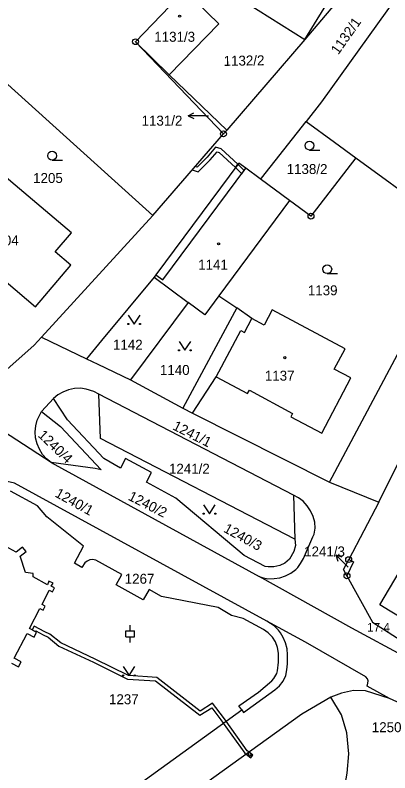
# Model space of a CAD drawing. Extents: x -562167 to -556918, y -1077891 to -1070763.
# Drawn here: x -559284.2 to -559220.3, y -1075093.3 to -1074964 of the extents above; entities that cross this region are included whole.
import ezdxf

# ---------------------------------------------------------------- set-up
doc = ezdxf.new("R2010")
doc.units = 0
for name, color, linetype in [('Hranice parcel', 7, 'Continuous'), ('Parcelní čísla', 7, 'Continuous'), ('Pop  PČ popisy', 7, 'Continuous'), ('Vnitřní kresba', 7, 'Continuous'), ('Věcná břemena k části', 7, 'Continuous'), ('Značky bodu BP', 7, 'Continuous'), ('Značky budov', 7, 'Continuous'), ('Značky kultur', 7, 'Continuous')]:
    doc.layers.add(name, color=color, linetype=linetype)

msp = doc.modelspace()

# ---------------------------------------------------------------- linework, layer by layer
at = {"layer": 'Hranice parcel'}
for p, q in [((-559263.69, -1074968.56), (-559255.3, -1074959.84)), ((-559257.93, -1074974.19), (-559263.69, -1074968.56)), ((-559248.71, -1074984.29), (-559263.69, -1074968.56)), ((-559260.73, -1074998.22), (-559290.13, -1074971.64)), ((-559248.14, -1074983.63), (-559257.93, -1074974.19)), ((-559260.73, -1074998.22), (-559248.71, -1074984.29)), ((-559248.71, -1074984.29), (-559248.14, -1074983.63)), ((-559237.44, -1074995.64), (-559242.45, -1074991.95)), ((-559237.44, -1074995.64), (-559249.47, -1075011.92)), ((-559279.73, -1075018.96), (-559260.73, -1074998.22)), ((-559260.54, -1075008.75), (-559254.74, -1075013.07)), ((-559249.47, -1075011.92), (-559246.45, -1075013.99)), ((-559254.74, -1075013.07), (-559264.53, -1075026.27)), ((-559246.45, -1075013.99), (-559255.63, -1075031.07)), ((-559279.73, -1075018.96), (-559272.06, -1075022.65)), ((-559264.53, -1075026.27), (-559255.63, -1075031.07)), ((-559277.69, -1075029.45), (-559279.74, -1075031.69)), ((-559236.78, -1075045.92), (-559269.97, -1075028.68)), ((-559255.63, -1075031.07), (-559253.99, -1075031.95)), ((-559253.99, -1075031.95), (-559230.63, -1075043.7)), ((-559278.07, -1075040.36), (-559242.63, -1075059.8)), ((-559222.24, -1075047.15), (-559218.86, -1075040.37)), ((-559230.63, -1075043.7), (-559222.24, -1075047.15)), ((-559236.78, -1075045.92), (-559236.54, -1075053.44)), ((-559222.24, -1075047.15), (-559227.36, -1075056.94)), ((-559206.67, -1075087.05), (-559220.42, -1075080.63)), ((-559272.93, -1075102.34), (-559245.59, -1075082.57))]:
    msp.add_line(p, q, dxfattribs=at)
for points in [[(-559238.79, -1074952.13), (-559240.62, -1074955.11), (-559244.8, -1074961.93), (-559234.81, -1074968.19), (-559226.15, -1074954.04), (-559222.92, -1074948.76), (-559232.94, -1074942.58), (-559236.16, -1074947.84), (-559238.79, -1074952.13)], [(-559216.47, -1074946.43), (-559234.81, -1074968.19), (-559248.14, -1074983.63)], [(-559217.7, -1074958.78), (-559231.97, -1074978.81), (-559234.61, -1074982.17)], [(-559255.3, -1074959.84), (-559249.47, -1074965.49), (-559257.93, -1074974.19)], [(-559242.45, -1074991.95), (-559242.24, -1074991.85), (-559234.61, -1074982.17)], [(-559234.61, -1074982.17), (-559229.78, -1074985.69), (-559226.12, -1074988.37)], [(-559307.05, -1075008), (-559298.84, -1074998.38), (-559280.72, -1075013.78), (-559274.69, -1075006.71), (-559277.38, -1075004.42), (-559274.61, -1075001.17), (-559284.23, -1074993.04), (-559289.72, -1074988.39), (-559292.44, -1074991.58), (-559292.75, -1074991.32), (-559296.55, -1074988.08), (-559309.68, -1075005.76)], [(-559242.45, -1074991.95), (-559244.9, -1074990.14), (-559246.1, -1074989.26), (-559260.23, -1075008.33), (-559260.54, -1075008.75)], [(-559226.12, -1074988.37), (-559233.79, -1074998.32), (-559237.44, -1074995.64)], [(-559226.12, -1074988.37), (-559213.81, -1074997.38), (-559208.23, -1075001.46)], [(-559230.63, -1075043.7), (-559208.82, -1075002.71), (-559208.23, -1075001.46)], [(-559260.54, -1075008.75), (-559269.5, -1075019.57), (-559272.06, -1075022.65)], [(-559249.47, -1075011.92), (-559251.89, -1075015.18), (-559254.74, -1075013.07)], [(-559253.99, -1075031.95), (-559249.93, -1075025.75), (-559244.61, -1075028.6), (-559244.29, -1075028), (-559236.93, -1075031.98), (-559237.24, -1075032.56), (-559231.96, -1075035.39), (-559226.97, -1075025.93), (-559229.81, -1075024.44), (-559227.96, -1075020.99), (-559240.41, -1075014.33), (-559241.74, -1075016.92), (-559243.87, -1075015.81), (-559246.45, -1075013.99)], [(-559278.07, -1075040.36), (-559293.43, -1075030.4), (-559312.19, -1075014.25)], [(-559286.13, -1075024.94), (-559280.96, -1075020.32), (-559279.73, -1075018.96)], [(-559272.06, -1075022.65), (-559270.1, -1075023.59), (-559264.53, -1075026.27)], [(-559269.97, -1075028.68), (-559270.78, -1075028.26), (-559272.09, -1075027.83), (-559273.08, -1075027.71), (-559274.11, -1075027.75), (-559275.1, -1075027.95), (-559276.08, -1075028.34), (-559276.94, -1075028.84), (-559277.69, -1075029.45)], [(-559236.54, -1075053.44), (-559236.41, -1075054.55), (-559236.69, -1075055.54), (-559237.45, -1075056.88), (-559238.22, -1075057.52), (-559239.12, -1075057.97), (-559240.1, -1075058.19), (-559241.1, -1075058.18), (-559241.6, -1075058.1), (-559245.16, -1075056.23), (-559256.82, -1075046.45), (-559261.82, -1075043.7), (-559260.95, -1075042.1), (-559265.37, -1075039.7), (-559266.27, -1075041.32), (-559269.09, -1075039.71), (-559275.26, -1075033.07), (-559277.69, -1075029.45)], [(-559236.54, -1075053.44), (-559269.65, -1075036.28), (-559269.97, -1075028.68)], [(-559278.07, -1075040.36), (-559278.85, -1075039.73), (-559279.52, -1075038.99), (-559280.08, -1075038.08), (-559280.48, -1075037.16), (-559280.72, -1075036.15), (-559280.78, -1075035.13), (-559280.69, -1075034.12), (-559280.43, -1075033.14), (-559279.74, -1075031.69)], [(-559279.74, -1075031.69), (-559276.45, -1075034.2), (-559269.53, -1075041.63), (-559270.56, -1075041.41), (-559278.07, -1075040.36)], [(-559241.32, -1075067.43), (-559284.34, -1075043.87), (-559286.56, -1075043.36), (-559289.11, -1075043.57), (-559289.97, -1075044.01)], [(-559245.59, -1075082.57), (-559246.08, -1075081.92), (-559242.72, -1075079.56), (-559240.46, -1075077.6), (-559240.11, -1075077.24), (-559239.62, -1075076.38), (-559239.49, -1075075.9), (-559239.32, -1075074.43), (-559239.34, -1075072.92), (-559239.51, -1075071.96), (-559239.86, -1075071), (-559240.37, -1075070.18), (-559241.06, -1075069.45), (-559241.88, -1075068.89), (-559245.36, -1075066.98), (-559247.31, -1075066.48), (-559249.62, -1075065.14), (-559259.25, -1075063.24), (-559261.39, -1075062.03), (-559262.36, -1075063.8), (-559266.98, -1075061.26), (-559266.05, -1075059.46), (-559270.48, -1075057.03), (-559271, -1075056.95), (-559271.48, -1075057), (-559271.95, -1075057.18), (-559272.35, -1075057.48), (-559272.83, -1075058.28), (-559274.09, -1075057.56), (-559272.55, -1075054.65), (-559278.78, -1075049.63), (-559280.41, -1075047.78), (-559284.98, -1075045.28)], [(-559242.63, -1075059.8), (-559242.13, -1075059.99), (-559241.12, -1075060.21), (-559240.08, -1075060.19), (-559239.08, -1075060.05), (-559238.12, -1075059.72), (-559237.21, -1075059.25), (-559236.39, -1075058.63), (-559236.03, -1075058.26), (-559235.55, -1075057.59), (-559235.06, -1075056.73), (-559233.45, -1075053.07), (-559233.26, -1075052.58), (-559233.08, -1075051.58), (-559233.14, -1075050.57), (-559233.44, -1075049.56), (-559233.85, -1075048.62), (-559234.41, -1075047.76), (-559235.1, -1075046.99), (-559235.9, -1075046.42), (-559236.78, -1075045.92)], [(-559196.58, -1075063.63), (-559203.73, -1075075.69), (-559220.31, -1075065.75), (-559222.06, -1075064.67), (-559218.74, -1075059.06), (-559213.37, -1075049.98), (-559200.62, -1075057.57), (-559200.89, -1075058.05), (-559197.29, -1075060.19)], [(-559284.83, -1075074.62), (-559283.63, -1075075.25), (-559283.19, -1075074.41), (-559284.39, -1075073.78), (-559282.18, -1075069.57), (-559280.98, -1075070.2), (-559280.54, -1075069.35), (-559281.74, -1075068.72), (-559279.98, -1075065.27), (-559279.43, -1075065.55), (-559279.08, -1075064.86), (-559279.62, -1075064.58), (-559278.4, -1075062.18), (-559277.84, -1075062.46), (-559277.49, -1075061.77), (-559278.04, -1075061.49), (-559277.72, -1075060.94), (-559278.44, -1075060.61), (-559278.67, -1075061.23), (-559281.16, -1075059.88), (-559281.12, -1075059.3), (-559282.45, -1075059.16), (-559283.33, -1075056.38), (-559282.32, -1075055.53), (-559282.93, -1075054.8), (-559284.03, -1075055.66), (-559286.53, -1075054.32)], [(-559227.65, -1075059.72), (-559228.25, -1075058.63), (-559227.36, -1075056.94)], [(-559227.36, -1075056.94), (-559226.52, -1075057.33), (-559227.65, -1075059.72)], [(-559215.74, -1075072.47), (-559216.62, -1075073.49), (-559217.48, -1075073.54), (-559217.55, -1075073.66), (-559226.8, -1075068.62), (-559242.63, -1075059.8)], [(-559227.65, -1075059.72), (-559223.32, -1075067.62), (-559215.74, -1075072.47)], [(-559245.59, -1075082.57), (-559245.27, -1075083.01), (-559241.99, -1075080.67), (-559239.93, -1075079.16), (-559239.16, -1075078.5), (-559238.53, -1075077.68), (-559238.1, -1075076.73), (-559237.9, -1075075.73), (-559237.79, -1075074.74), (-559237.77, -1075073.2), (-559237.87, -1075072.17), (-559238.12, -1075071.17), (-559238.5, -1075070.26), (-559238.99, -1075069.41), (-559239.31, -1075068.98), (-559240.06, -1075068.27), (-559241.32, -1075067.43)], [(-559220.42, -1075080.63), (-559224.2, -1075078.56), (-559224.07, -1075078), (-559224.05, -1075077.6), (-559224.18, -1075077.26), (-559224.45, -1075076.95), (-559234.7, -1075071.05), (-559241.32, -1075067.43)], [(-559220.42, -1075080.63), (-559224.47, -1075079.31), (-559226.54, -1075079.27), (-559228.58, -1075079.75), (-559230.4, -1075080.42)], [(-559230.4, -1075080.42), (-559235.33, -1075083.33), (-559264.92, -1075104.67)], [(-559230.7, -1075102.99), (-559229.22, -1075099.97), (-559229.03, -1075099.36), (-559228.19, -1075096.62), (-559227.62, -1075093.4), (-559227.33, -1075090.1), (-559227.69, -1075086.51), (-559228.61, -1075083.41), (-559230.4, -1075080.42)]]:
    msp.add_lwpolyline(points, dxfattribs=at)
at = {"layer": 'Pop  PČ popisy'}
for p, q in [((-559254.73, -1074981.18), (-559253.73, -1074980.68)), ((-559251.73, -1074981.18), (-559254.73, -1074981.18)), ((-559254.73, -1074981.18), (-559253.73, -1074981.68)), ((-559251.73, -1074981.18), (-559251.23, -1074981.18)), ((-559227.46, -1075058.24), (-559229.58, -1075056.12)), ((-559229.58, -1075056.12), (-559228.52, -1075056.47)), ((-559229.58, -1075056.12), (-559229.23, -1075057.18))]:
    msp.add_line(p, q, dxfattribs=at)
at = {"layer": 'Vnitřní kresba'}
for p, q in [((-559259.04, -1075009.22), (-559244.9, -1074990.14)), ((-559260.23, -1075008.33), (-559259.04, -1075009.22)), ((-559245.11, -1075018.17), (-559243.87, -1075015.81)), ((-559249.93, -1075025.75), (-559245.75, -1075017.83)), ((-559245.75, -1075017.83), (-559245.11, -1075018.17))]:
    msp.add_line(p, q, dxfattribs=at)
at = {"layer": 'Věcná břemena k části'}
for points in [[(-559253.01, -1074990.78), (-559250.98, -1074988.73), (-559249.8, -1074987.37), (-559249.45, -1074987.47), (-559246.65, -1074990), (-559246.23, -1074989.43), (-559249.11, -1074986.84), (-559250.04, -1074986.57), (-559251.5, -1074988.25), (-559253.19, -1074989.98), (-559253.52, -1074989.87), (-559254.02, -1074990.44)], [(-559245.6, -1074991.08), (-559245.17, -1074990.51), (-559246.23, -1074989.43), (-559246.65, -1074990)], [(-559281.3, -1075068.95), (-559280.77, -1075069.23), (-559280.7, -1075069.11), (-559279.42, -1075069.79), (-559278.6, -1075070.19), (-559276.74, -1075071.69), (-559270.83, -1075074.45), (-559265.03, -1075077.32), (-559260.28, -1075077.62), (-559252.73, -1075083.5), (-559250.7, -1075082.26), (-559249.16, -1075084.26), (-559248.74, -1075084.85), (-559245.08, -1075089.97), (-559244.82, -1075090.17), (-559244.31, -1075089.81), (-559244.64, -1075089.55), (-559248.25, -1075084.5), (-559248.68, -1075083.9), (-559250.56, -1075081.46), (-559252.69, -1075082.78), (-559260.06, -1075077.04), (-559264.87, -1075076.72), (-559270.57, -1075073.91), (-559276.42, -1075071.17), (-559278.28, -1075069.69), (-559279.14, -1075069.25), (-559280.94, -1075068.29)], [(-559243.67, -1075090.31), (-559244.31, -1075089.81), (-559244.82, -1075090.17), (-559244.04, -1075090.78)], [(-559244.26, -1075090.5), (-559243.92, -1075090.28), (-559244.24, -1075089.76), (-559244.57, -1075090)]]:
    msp.add_lwpolyline(points, close=True, dxfattribs=at)
at = {"layer": 'Značky bodu BP'}
for centre, radius in [((-559263.69, -1074968.56), 0.5), ((-559263.69, -1074968.56), 0.0303), ((-559248.71, -1074984.29), 0.5), ((-559248.71, -1074984.29), 0.0303), ((-559233.79, -1074998.32), 0.5), ((-559233.79, -1074998.32), 0.0303), ((-559227.36, -1075056.94), 0.5), ((-559227.36, -1075056.94), 0.0303), ((-559227.65, -1075059.72), 0.5), ((-559227.65, -1075059.72), 0.0303)]:
    msp.add_circle(centre, radius, dxfattribs=at)
at = {"layer": 'Značky budov'}
for centre in [(-559256.17, -1074964.21), (-559249.53, -1075003.07), (-559238.24, -1075022.48)]:
    msp.add_circle(centre, 0.175, dxfattribs=at)
at = {"layer": 'Značky kultur'}
for p, q in [((-559234.05, -1074987.04), (-559232.3, -1074987.04)), ((-559277.91, -1074988.76), (-559276.16, -1074988.76)), ((-559231.01, -1075008.14), (-559229.26, -1075008.14)), ((-559264.61, -1075069.1), (-559264.61, -1075068.1)), ((-559265.36, -1075069.1), (-559263.86, -1075069.1)), ((-559265.36, -1075070.1), (-559265.36, -1075069.1)), ((-559263.86, -1075070.1), (-559263.86, -1075069.1)), ((-559265.36, -1075070.1), (-559263.86, -1075070.1)), ((-559264.61, -1075071.1), (-559264.61, -1075070.1))]:
    msp.add_line(p, q, dxfattribs=at)
for points in [[(-559264.92, -1075015.24), (-559263.92, -1075016.74), (-559262.92, -1075015.24)], [(-559256.28, -1075019.72), (-559255.28, -1075021.22), (-559254.28, -1075019.72)], [(-559252.09, -1075047.61), (-559251.09, -1075049.11), (-559250.09, -1075047.61)], [(-559265.8, -1075075.19), (-559264.8, -1075076.69), (-559263.8, -1075075.19)]]:
    msp.add_lwpolyline(points, dxfattribs=at)
for centre, radius in [((-559234.05, -1074986.29), 0.75), ((-559277.91, -1074988.01), 0.75), ((-559231.01, -1075007.39), 0.75), ((-559264.92, -1075016.74), 0.1), ((-559262.92, -1075016.74), 0.1), ((-559256.28, -1075021.22), 0.1), ((-559254.28, -1075021.22), 0.1), ((-559252.09, -1075049.11), 0.1), ((-559250.09, -1075049.11), 0.1), ((-559265.8, -1075076.69), 0.1), ((-559263.8, -1075076.69), 0.1)]:
    msp.add_circle(centre, radius, dxfattribs=at)

# ---------------------------------------------------------------- texts
at = {"layer": 'Parcelní čísla'}
for s, rotation, p in [('1132/1', 55, (-559229.13, -1074970.88)), ('1132/2', 1, (-559248.66, -1074972.69)), ('1241/1', 333, (-559257.5, -1075034.66)), ('1240/4', 316, (-559280.43, -1075035.85)), ('1240/1', 331, (-559277.56, -1075046.12)), ('1240/2', 333, (-559265.08, -1075046.67)), ('1240/3', 331, (-559248.83, -1075052.13))]:
    msp.add_text(s, height=1.7, rotation=rotation, dxfattribs=at).set_placement(p)
for s, p in [('1131/3', (-559260.49, -1074968.57)), ('1131/2', (-559262.66, -1074982.88)), ('1138/2', (-559237.93, -1074991.14)), ('1205', (-559281.14, -1074992.67)), ('1204', (-559288.66, -1075003.32)), ('1141', (-559253.01, -1075007.46)), ('1139', (-559234.32, -1075011.83)), ('1142', (-559267.53, -1075021.11)), ('1140', (-559259.53, -1075025.43)), ('1137', (-559241.65, -1075026.4)), ('1241/2', (-559257.99, -1075042.28)), ('1241/3', (-559234.95, -1075056.4)), ('1267', (-559265.53, -1075061.06)), ('1237', (-559268.21, -1075081.62)), ('1250', (-559223.42, -1075086.39))]:
    msp.add_text(s, height=1.7, dxfattribs=at).set_placement(p)
at = {"layer": 'Značky bodu BP'}
msp.add_text('17.4', height=1.5, dxfattribs=at).set_placement((-559224.23, -1075069.24))

doc.saveas('drawing.dxf')
